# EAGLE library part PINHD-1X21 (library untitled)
PIN HEADER
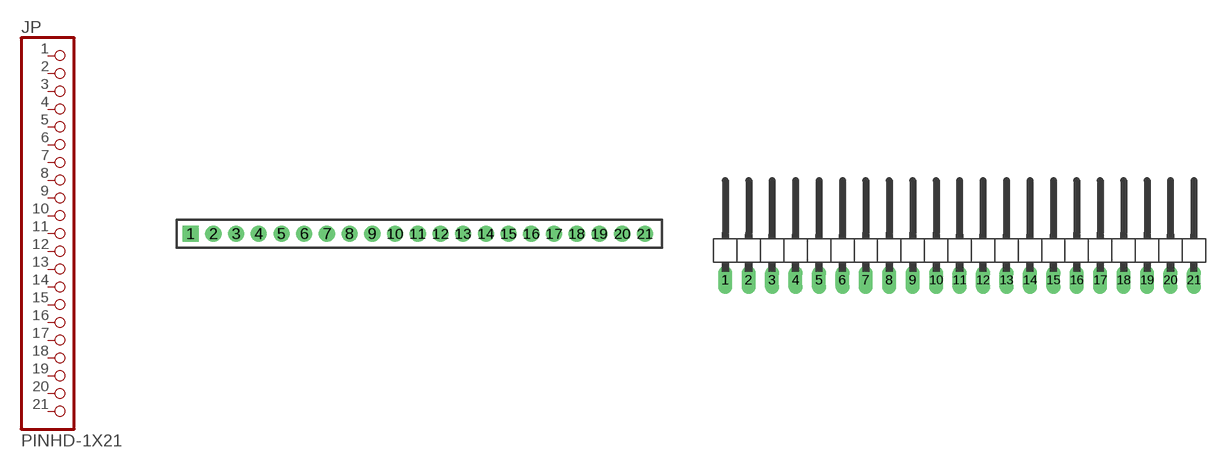
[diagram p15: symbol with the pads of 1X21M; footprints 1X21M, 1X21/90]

Designator prefix JP

## PINHD-1X21_2.00  [1X21M]
1  1  pas
2  2  pas
3  3  pas
4  4  pas
5  5  pas
6  6  pas
7  7  pas
8  8  pas
9  9  pas
10  10  pas
11  11  pas
12  12  pas
13  13  pas
14  14  pas
15  15  pas
16  16  pas
17  17  pas
18  18  pas
19  19  pas
20  20  pas
21  21  pas

## PINHD-1X21_2.54-90°  [1X21/90]
Pads as for 1X21M

## PINHD-1X21_2.54-90°-S  [1X21/90-S]
Pads as for 1X21M

## PINHD-1X21_2.54  [1X21]
Pads as for 1X21M

## PINHD-1X21_2.54-S  [1X21-S]
Pads as for 1X21M

## PINHD-1X21_2.54-SMD  [1X21SMD]
Pads as for 1X21M

## PINHD-1X21_2.54-SMD-90°  [1X21SMD/90]
Pads as for 1X21M

## Footprint 1X21M (pad centres in mm)
PIN HEADER - 2
drill 0.914 square: 1 -19,0
drill 0.914 round: 2 -17,0; 3 -15,0; 4 -13,0; 5 -11,0; 6 -9,0; 7 -7,0; 8 -5,0; 9 -3,0; 10 -1,0; 11 1,0; 12 3,0; 13 5,0; 14 7,0; 15 9,0; 16 11,0; 17 13,0; 18 15,0; 19 17,0; 20 19,0; 21 21,0

## Footprint 1X21/90 (pad centres in mm)
PIN HEADER - 2.54 90°
drill 1.016 long: 1 -24.13,-3.81; 2 -21.59,-3.81; 3 -19.05,-3.81; 4 -16.51,-3.81; 5 -13.97,-3.81; 6 -11.43,-3.81; 7 -8.89,-3.81; 8 -6.35,-3.81; 9 -3.81,-3.81; 10 -1.27,-3.81; 11 1.27,-3.81; 12 3.81,-3.81; 13 6.35,-3.81; 14 8.89,-3.81; 15 11.43,-3.81; 16 13.97,-3.81; 17 16.51,-3.81; 18 19.05,-3.81; 19 21.59,-3.81; 20 24.13,-3.81; 21 26.67,-3.81

## Footprint 1X21/90-S (pad centres in mm)
PIN HEADER - 2.54 90°
drill 1.016 square: 1 -24.13,-3.81
drill 1.016 octagon: 2 -21.59,-3.81; 3 -19.05,-3.81; 4 -16.51,-3.81; 5 -13.97,-3.81; 6 -11.43,-3.81; 7 -8.89,-3.81; 8 -6.35,-3.81; 9 -3.81,-3.81; 10 -1.27,-3.81; 11 1.27,-3.81; 12 3.81,-3.81; 13 6.35,-3.81; 14 8.89,-3.81; 15 11.43,-3.81; 16 13.97,-3.81; 17 16.51,-3.81; 18 19.05,-3.81; 19 21.59,-3.81; 20 24.13,-3.81; 21 26.67,-3.81

## Footprint 1X21 (pad centres in mm)
PIN HEADER - 2.54
drill 1.016 long: 1 -24.13,0; 2 -21.59,0; 3 -19.05,0; 4 -16.51,0; 5 -13.97,0; 6 -11.43,0; 7 -8.89,0; 8 -6.35,0; 9 -3.81,0; 10 -1.27,0; 11 1.27,0; 12 3.81,0; 13 6.35,0; 14 8.89,0; 15 11.43,0; 16 13.97,0; 17 16.51,0; 18 19.05,0; 19 21.59,0; 20 24.13,0; 21 26.67,0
